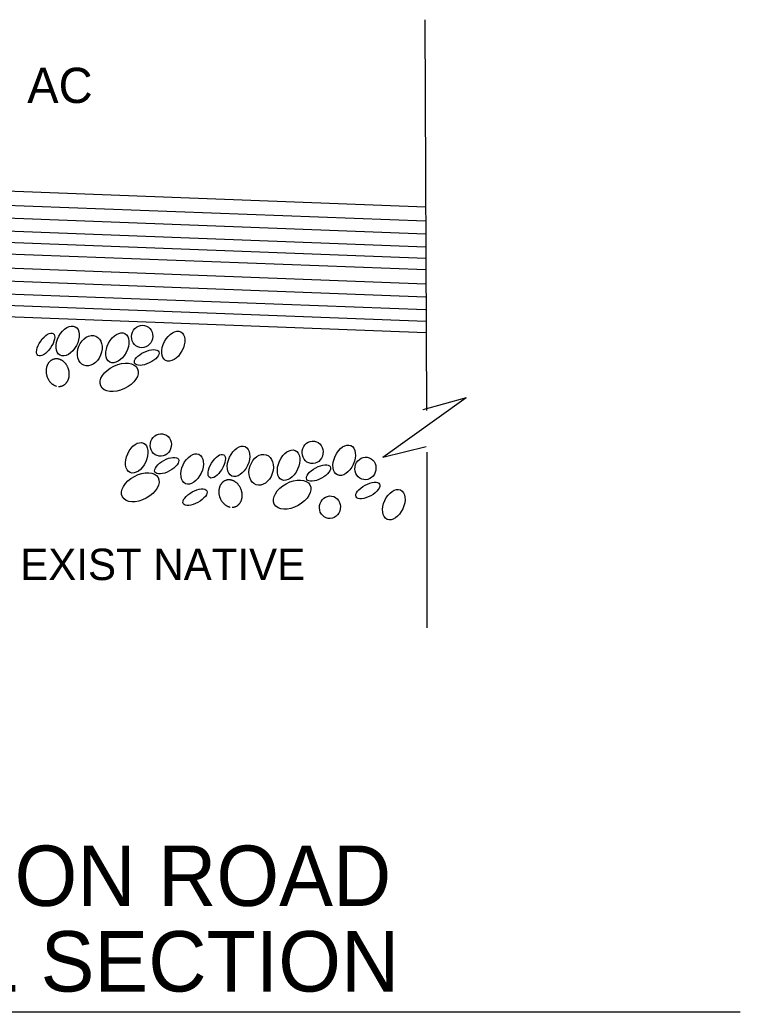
# Model space of a CAD drawing. Extents: x 6710407 to 6714861, y 1868090 to 1871317.
# Drawn here: x 6713375.5 to 6713518.7, y 1871079.8 to 1871277 of the extents above; entities that cross this region are included whole.
import ezdxf

# ---------------------------------------------------------------- set-up
doc = ezdxf.new("R2010")
doc.units = 0
doc.layers.add('Nongeo Data(60)', color=7, linetype='Continuous')
doc.layers.add('Sndwall Anno(59)', color=7, linetype='Continuous')

# ---------------------------------------------------------------- blocks, each defined once
blk = doc.blocks.new('ELLIPS')
at = {"layer": 'Sndwall Anno(59)'}
blk.add_circle((0, 0), 0.0254, dxfattribs=at)
blk = doc.blocks.new('SHORTN')
at = {"layer": 'Sndwall Anno(59)'}
for p, q in [((-0.00193, 0), (-0.00259, 0.00447)), ((0.00264, -0.00447), (-0.00259, 0.00447)), ((-0.00193, 0), (-0.00193, 0)), ((0.00264, -0.00447), (0.00183, 0)), ((0.00183, 0), (0.00183, 0))]:
    blk.add_line(p, q, dxfattribs=at)

msp = doc.modelspace()

# ---------------------------------------------------------------- linework, layer by layer
at = {"layer": 'Nongeo Data(60)'}
for p, q in [((6713456.43, 1871199.41), (6713456.06, 1871277.05)), ((6713274.72, 1871246.8), (6713456.12, 1871239.91)), ((6713274.7, 1871243.96), (6713456.13, 1871237.07)), ((6713274.69, 1871241.41), (6713456.14, 1871234.51)), ((6713274.68, 1871238.85), (6713456.16, 1871231.95)), ((6713274.67, 1871236.58), (6713456.17, 1871229.68)), ((6713274.65, 1871234.3), (6713456.18, 1871227.4)), ((6713274.7, 1871231.45), (6713456.13, 1871224.56)), ((6713274.69, 1871228.9), (6713456.14, 1871222)), ((6713274.68, 1871226.34), (6713456.16, 1871219.45)), ((6713274.67, 1871224.07), (6713456.17, 1871217.17)), ((6713274.65, 1871221.79), (6713456.18, 1871214.89)), ((6713456.46, 1871156.24), (6713456.48, 1871191.09)), ((6713518.7, 1871079.82), (6713243.97, 1871079.82))]:
    msp.add_line(p, q, dxfattribs=at)
for points in [[(6713382.37, 1871209.63), (6713382.29, 1871209.62), (6713382.22, 1871209.6), (6713382.14, 1871209.57), (6713382.07, 1871209.54), (6713381.99, 1871209.51), (6713381.92, 1871209.48), (6713381.85, 1871209.44), (6713381.78, 1871209.4), (6713381.71, 1871209.36), (6713381.65, 1871209.31), (6713381.58, 1871209.26), (6713381.52, 1871209.21), (6713381.46, 1871209.16), (6713381.4, 1871209.1), (6713381.34, 1871209.04), (6713381.29, 1871208.98), (6713381.24, 1871208.91), (6713381.19, 1871208.85), (6713381.14, 1871208.78), (6713381.09, 1871208.7), (6713381.05, 1871208.63), (6713381.01, 1871208.55), (6713380.97, 1871208.47), (6713380.93, 1871208.39), (6713380.9, 1871208.31), (6713380.87, 1871208.23), (6713380.84, 1871208.14), (6713380.81, 1871208.06), (6713380.79, 1871207.97), (6713380.77, 1871207.88), (6713380.75, 1871207.79), (6713380.74, 1871207.7), (6713380.72, 1871207.6), (6713380.71, 1871207.51), (6713380.71, 1871207.42), (6713380.7, 1871207.32), (6713380.7, 1871207.23), (6713380.7, 1871207.13), (6713380.71, 1871207.04), (6713380.71, 1871206.94), (6713380.72, 1871206.84), (6713380.74, 1871206.75), (6713380.75, 1871206.65), (6713380.77, 1871206.56), (6713380.79, 1871206.46), (6713380.82, 1871206.37), (6713380.84, 1871206.28), (6713380.87, 1871206.18), (6713380.9, 1871206.09), (6713380.94, 1871206), (6713380.98, 1871205.91), (6713381.02, 1871205.82), (6713381.06, 1871205.74), (6713381.1, 1871205.65), (6713381.15, 1871205.57), (6713381.2, 1871205.48), (6713381.25, 1871205.4), (6713381.3, 1871205.32), (6713381.36, 1871205.25), (6713381.41, 1871205.17), (6713381.47, 1871205.1), (6713381.53, 1871205.03), (6713381.6, 1871204.96), (6713381.66, 1871204.9), (6713381.73, 1871204.83), (6713381.8, 1871204.77), (6713381.86, 1871204.71), (6713381.94, 1871204.66), (6713382.01, 1871204.61), (6713382.08, 1871204.56), (6713382.15, 1871204.51), (6713382.23, 1871204.47), (6713382.31, 1871204.43), (6713382.38, 1871204.39), (6713382.46, 1871204.35), (6713382.54, 1871204.32), (6713382.62, 1871204.29), (6713382.7, 1871204.27), (6713382.78, 1871204.25)], [(6713383.16, 1871204.19), (6713383.24, 1871204.19), (6713383.32, 1871204.19), (6713383.4, 1871204.19), (6713383.48, 1871204.2), (6713383.56, 1871204.21), (6713383.64, 1871204.22), (6713383.72, 1871204.24), (6713383.79, 1871204.26), (6713383.87, 1871204.29), (6713383.94, 1871204.31), (6713384.02, 1871204.34), (6713384.09, 1871204.38), (6713384.16, 1871204.41), (6713384.23, 1871204.45), (6713384.29, 1871204.5), (6713384.36, 1871204.54), (6713384.43, 1871204.59), (6713384.49, 1871204.64), (6713384.55, 1871204.7), (6713384.61, 1871204.75), (6713384.67, 1871204.81), (6713384.72, 1871204.87), (6713384.77, 1871204.94), (6713384.82, 1871205.01), (6713384.87, 1871205.08), (6713384.92, 1871205.15), (6713384.96, 1871205.22), (6713385, 1871205.3), (6713385.04, 1871205.38), (6713385.08, 1871205.46), (6713385.11, 1871205.54), (6713385.15, 1871205.62), (6713385.18, 1871205.71), (6713385.2, 1871205.79), (6713385.23, 1871205.88), (6713385.25, 1871205.97), (6713385.26, 1871206.06), (6713385.28, 1871206.15), (6713385.29, 1871206.24), (6713385.3, 1871206.34), (6713385.31, 1871206.43), (6713385.31, 1871206.53), (6713385.32, 1871206.62), (6713385.31, 1871206.72), (6713385.31, 1871206.81), (6713385.3, 1871206.91), (6713385.29, 1871207), (6713385.28, 1871207.1), (6713385.26, 1871207.2), (6713385.25, 1871207.29), (6713385.23, 1871207.39), (6713385.2, 1871207.48), (6713385.18, 1871207.57), (6713385.15, 1871207.67), (6713385.12, 1871207.76), (6713385.08, 1871207.85), (6713385.05, 1871207.94), (6713385.01, 1871208.03), (6713384.96, 1871208.11), (6713384.92, 1871208.2), (6713384.87, 1871208.28), (6713384.83, 1871208.37), (6713384.78, 1871208.45), (6713384.72, 1871208.53), (6713384.67, 1871208.6), (6713384.61, 1871208.68), (6713384.55, 1871208.75), (6713384.49, 1871208.82), (6713384.43, 1871208.89), (6713384.36, 1871208.96), (6713384.3, 1871209.02), (6713384.23, 1871209.08), (6713384.16, 1871209.14), (6713384.09, 1871209.19), (6713384.02, 1871209.25), (6713383.94, 1871209.3), (6713383.87, 1871209.34), (6713383.8, 1871209.39), (6713383.72, 1871209.43), (6713383.64, 1871209.47), (6713383.56, 1871209.5), (6713383.49, 1871209.53), (6713383.41, 1871209.56), (6713383.33, 1871209.59), (6713383.25, 1871209.61), (6713383.17, 1871209.63), (6713383.09, 1871209.64), (6713383, 1871209.66), (6713382.92, 1871209.67), (6713382.84, 1871209.67), (6713382.76, 1871209.67), (6713382.68, 1871209.67), (6713382.6, 1871209.67), (6713382.52, 1871209.66), (6713382.45, 1871209.65), (6713382.37, 1871209.63)], [(6713416.56, 1871185.56), (6713416.49, 1871185.53), (6713416.41, 1871185.51), (6713416.34, 1871185.48), (6713416.27, 1871185.45), (6713416.19, 1871185.41), (6713416.13, 1871185.37), (6713416.06, 1871185.33), (6713415.99, 1871185.29), (6713415.93, 1871185.24), (6713415.86, 1871185.19), (6713415.8, 1871185.14), (6713415.74, 1871185.08), (6713415.69, 1871185.03), (6713415.63, 1871184.96), (6713415.58, 1871184.9), (6713415.53, 1871184.84), (6713415.48, 1871184.77), (6713415.43, 1871184.7), (6713415.39, 1871184.62), (6713415.34, 1871184.55), (6713415.31, 1871184.47), (6713415.27, 1871184.39), (6713415.23, 1871184.31), (6713415.2, 1871184.23), (6713415.17, 1871184.15), (6713415.15, 1871184.06), (6713415.12, 1871183.98), (6713415.1, 1871183.89), (6713415.09, 1871183.8), (6713415.07, 1871183.71), (6713415.06, 1871183.62), (6713415.05, 1871183.52), (6713415.04, 1871183.43), (6713415.04, 1871183.34), (6713415.04, 1871183.24), (6713415.04, 1871183.15), (6713415.04, 1871183.05), (6713415.05, 1871182.96), (6713415.06, 1871182.86), (6713415.07, 1871182.77), (6713415.09, 1871182.67), (6713415.11, 1871182.58), (6713415.13, 1871182.48), (6713415.15, 1871182.39), (6713415.18, 1871182.3), (6713415.21, 1871182.2), (6713415.24, 1871182.11), (6713415.28, 1871182.02), (6713415.32, 1871181.93), (6713415.35, 1871181.84), (6713415.4, 1871181.76), (6713415.44, 1871181.67), (6713415.49, 1871181.59), (6713415.54, 1871181.5), (6713415.59, 1871181.42), (6713415.64, 1871181.34), (6713415.7, 1871181.26), (6713415.76, 1871181.19), (6713415.82, 1871181.12), (6713415.88, 1871181.05), (6713415.94, 1871180.98), (6713416.01, 1871180.91), (6713416.07, 1871180.85), (6713416.14, 1871180.78), (6713416.21, 1871180.73), (6713416.28, 1871180.67), (6713416.36, 1871180.62), (6713416.43, 1871180.56), (6713416.51, 1871180.52), (6713416.58, 1871180.47), (6713416.66, 1871180.43), (6713416.74, 1871180.39), (6713416.81, 1871180.35), (6713416.89, 1871180.32), (6713416.97, 1871180.29), (6713417.05, 1871180.26), (6713417.14, 1871180.24), (6713417.22, 1871180.22), (6713417.3, 1871180.2)], [(6713417.68, 1871180.17), (6713417.76, 1871180.17), (6713417.84, 1871180.18), (6713417.92, 1871180.19), (6713418, 1871180.2), (6713418.08, 1871180.21), (6713418.16, 1871180.23), (6713418.23, 1871180.25), (6713418.31, 1871180.28), (6713418.38, 1871180.31), (6713418.45, 1871180.34), (6713418.53, 1871180.37), (6713418.6, 1871180.41), (6713418.66, 1871180.45), (6713418.73, 1871180.5), (6713418.8, 1871180.54), (6713418.86, 1871180.59), (6713418.92, 1871180.65), (6713418.98, 1871180.7), (6713419.04, 1871180.76), (6713419.09, 1871180.82), (6713419.15, 1871180.88), (6713419.2, 1871180.95), (6713419.25, 1871181.01), (6713419.29, 1871181.09), (6713419.34, 1871181.16), (6713419.38, 1871181.23), (6713419.42, 1871181.31), (6713419.46, 1871181.39), (6713419.49, 1871181.47), (6713419.52, 1871181.55), (6713419.55, 1871181.63), (6713419.58, 1871181.72), (6713419.6, 1871181.8), (6713419.62, 1871181.89), (6713419.64, 1871181.98), (6713419.66, 1871182.07), (6713419.67, 1871182.16), (6713419.68, 1871182.26), (6713419.69, 1871182.35), (6713419.69, 1871182.44), (6713419.69, 1871182.54), (6713419.69, 1871182.63), (6713419.69, 1871182.73), (6713419.68, 1871182.82), (6713419.67, 1871182.92), (6713419.66, 1871183.01), (6713419.64, 1871183.11), (6713419.62, 1871183.2), (6713419.6, 1871183.3), (6713419.58, 1871183.39), (6713419.55, 1871183.48), (6713419.52, 1871183.58), (6713419.49, 1871183.67), (6713419.45, 1871183.76), (6713419.42, 1871183.85), (6713419.38, 1871183.94), (6713419.34, 1871184.03), (6713419.29, 1871184.11), (6713419.25, 1871184.2), (6713419.2, 1871184.28), (6713419.15, 1871184.36), (6713419.09, 1871184.44), (6713419.04, 1871184.52), (6713418.98, 1871184.59), (6713418.92, 1871184.67), (6713418.86, 1871184.74), (6713418.79, 1871184.81), (6713418.73, 1871184.87), (6713418.66, 1871184.94), (6713418.59, 1871185), (6713418.52, 1871185.06), (6713418.45, 1871185.12), (6713418.38, 1871185.17), (6713418.31, 1871185.22), (6713418.23, 1871185.27), (6713418.16, 1871185.31), (6713418.08, 1871185.36), (6713418, 1871185.4), (6713417.92, 1871185.43), (6713417.84, 1871185.47), (6713417.76, 1871185.5), (6713417.68, 1871185.52), (6713417.6, 1871185.55), (6713417.52, 1871185.57), (6713417.44, 1871185.58), (6713417.36, 1871185.6), (6713417.28, 1871185.61), (6713417.2, 1871185.62), (6713417.12, 1871185.62), (6713417.03, 1871185.62), (6713416.95, 1871185.62), (6713416.87, 1871185.61), (6713416.8, 1871185.6), (6713416.72, 1871185.59), (6713416.64, 1871185.58), (6713416.56, 1871185.56)]]:
    msp.add_lwpolyline(points, dxfattribs=at)

# ---------------------------------------------------------------- block references
for name, p, xscale, yscale, rotation in [('ELLIPS', (6713384.98, 1871213.22), 126.36448405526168, 77.62159697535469, -118.00175424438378), ('ELLIPS', (6713399.8, 1871214.12), 88.60251698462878, 82.27024960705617, -102.23975451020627), ('ELLIPS', (6713380.6, 1871212.52), 104.77652932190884, 46.89631374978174, -124.92075513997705), ('ELLIPS', (6713389.38, 1871211.28), 123.27450099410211, 91.90688995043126, -112.28075428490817), ('ELLIPS', (6713394.87, 1871211.86), 126.36448405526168, 77.62159697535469, -118.00175424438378), ('ELLIPS', (6713405.98, 1871212.18), 126.36448405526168, 77.62159697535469, -118.00175424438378), ('ELLIPS', (6713400.72, 1871209.94), 104.77652873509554, 46.89631374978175, -154.9207546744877), ('ELLIPS', (6713395.23, 1871205.99), 158.74648473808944, 97.16070059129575, 25.111245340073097), ('SHORTN', (6713455.92, 1871195.95), 1968.5039370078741, 1968.5039370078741, 95.36061039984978), ('ELLIPS', (6713403.51, 1871192.55), 88.60251795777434, 82.27024960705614, -98.78216440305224), ('ELLIPS', (6713398.72, 1871190), 126.36448330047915, 77.62159697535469, -114.54416357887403), ('ELLIPS', (6713418.96, 1871189.3), 126.36448330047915, 77.62159697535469, -114.54416357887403), ('ELLIPS', (6713433.69, 1871191.09), 88.60251795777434, 82.27024960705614, -98.78216440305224), ('ELLIPS', (6713439.97, 1871189.52), 126.36448330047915, 77.62159697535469, -114.54416357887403), ('ELLIPS', (6713409.74, 1871187.78), 126.36448330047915, 77.62159697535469, -114.54416357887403), ('ELLIPS', (6713414.62, 1871188.33), 104.77653124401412, 46.89631374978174, -121.4631647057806), ('ELLIPS', (6713423.47, 1871187.62), 123.2744999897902, 91.90688995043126, -108.82316321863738), ('ELLIPS', (6713428.91, 1871188.54), 126.36448330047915, 77.62159697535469, -114.54416357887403), ('ELLIPS', (6713404.68, 1871188.44), 104.77652940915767, 46.89631374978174, -151.4631641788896), ('ELLIPS', (6713434.87, 1871186.97), 104.77652940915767, 46.89631374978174, -151.4631641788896), ('ELLIPS', (6713444.2, 1871187.89), 88.60251795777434, 82.27024960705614, -98.78216440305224), ('ELLIPS', (6713399.43, 1871184.15), 158.74648516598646, 97.16070059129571, 28.568836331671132), ('ELLIPS', (6713429.62, 1871182.69), 158.74648516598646, 97.16070059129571, 28.568836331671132), ('ELLIPS', (6713444.68, 1871183.51), 104.77652940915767, 46.89631374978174, -151.4631641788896), ('ELLIPS', (6713410.31, 1871182.17), 104.77652940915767, 46.89631374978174, -151.4631641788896), ('ELLIPS', (6713449.83, 1871180.69), 126.36448330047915, 77.62159697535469, -114.54416357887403), ('ELLIPS', (6713437.13, 1871180.17), 88.60251795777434, 82.27024960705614, -98.78216440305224)]:
    msp.add_blockref(name, p, dxfattribs=dict(at, xscale=xscale, yscale=yscale, rotation=rotation))

# ---------------------------------------------------------------- texts
for s, height, p in [('AC', 7, (6713376.95, 1871260.52)), ('EXIST NATIVE', 6.2487, (6713375.56, 1871165.7)), ('TYP CALIBRATION ROAD', 12, (6713255.84, 1871100.93)), ('STRUCTURAL SECTION', 12, (6713267.27, 1871083.92))]:
    msp.add_text(s, height=height, dxfattribs=at).set_placement(p)

doc.saveas('drawing.dxf')
